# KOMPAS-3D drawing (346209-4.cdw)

Referenced files in E:\Паша\Компас\Курсовая\: С1.cdw
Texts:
  КП.ОКМЧЕП.МЕ.12-01.000СП
  Редуктор циліндричний  одноступінчатий
  Текст на чертеже
  Размерные надписи
  Шероховатость
  Линия-выноска #1
  Линия-выноска #2
  Линия-выноска #3
  Отклонения формы и база
  Заголовок таблицы
  Ячейка таблицы
  Стрелка вида
  Обозначение изменения
  Фигурная скобка
  Номер узла
  Марка координационной оси
  VRCB
  Выносная надпись
  Обозначение узла
  Марка/позиционное обозначение с линией-выноской
  Марка/позиционное обозначение на линии
  Марка/позиционное обозначение без линии-выноски
  КП.ОКМЧЕП.МЕ.12-01.000 СК
  Документація
  Складальне креслення
  Складальні одиниці
  КП.ОКМЧЕП.МЕ.12-01.001
  КП.ОКМЧЕП.МЕ.12-01.002
  КП.ОКМЧЕП.МЕ.12-01.003
  КП.ОКМЧЕП.МЕ.12-01.004
  КП.ОКМЧЕП.МЕ.12-01.005
  КП.ОКМЧЕП.МЕ.12-01.006
  КП.ОКМЧЕП.МЕ.12-01.007
  КП.ОКМЧЕП.МЕ.12-01.008
  КП.ОКМЧЕП.МЕ.12-01.009
  КП.ОКМЧЕП.МЕ.12-01.010
  КП.ОКМЧЕП.МЕ.12-01.011
  КП.ОКМЧЕП.МЕ.12-01.012
  КП.ОКМЧЕП.МЕ.12-01.013
  КП.ОКМЧЕП.МЕ.12-01.014
  КП.ОКМЧЕП.МЕ.12-01.015
  КП.ОКМЧЕП.МЕ.12-01.016
  КП.ОКМЧЕП.МЕ.12-01.017
  Корпус
  Кришка корпуса
  Ведене зубчасте колесо
  Ведуче зубчасте колесо
  Вал ведений
  Вал ведучий
  Кришка підшипника скрізна
  Кришка підшипника глуха
  Кільце маслоутримуюче
  Кільце дистанційне
  Стандартні вироби
  Манжети ГОСТ 8752-79
  Шарівський Я. В.
  Редуктор циліндричний
  одноступінчатий
  Таран В. В.
  ПолтНТУ гр.301-МЕ
  КП.ОКМЧЕП.МЕ.11.01.000СП-
  КП.ОКМЧЕП.МЕ.12-01.018
  КП.ОКМЧЕП.МЕ.12-01.041
  Деталі
Dimensions and other numbers on the sheet: 7; 1:1; 1; 2; 3; 4; 5; 6; 8; 9; 10; 11; 12; 13; 14; 15; 16; 17; 2009; 18; 39; 0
